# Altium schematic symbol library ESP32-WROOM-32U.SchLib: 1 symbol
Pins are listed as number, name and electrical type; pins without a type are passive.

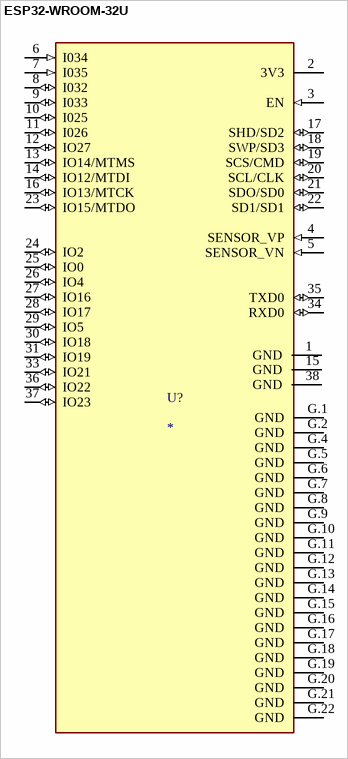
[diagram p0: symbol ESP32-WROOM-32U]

## ESP32-WROOM-32U
designator U?
Bluetooth, WiFi 802.11b/g/n, Bluetooth v4.2 +EDR, Class 1, 2 and 3 Transceiver Module 2.4GHz ~ 2.5GHz Antenna Not Included, U.FL Surface Mount; MF: Espressif Systems; MP: ESP32-WROOM-32U
footprint ESP32-WROOM-32U
pins: 1 GND (power), 2 3V3 (power), 3 EN (in), 4 SENSOR_VP (in), 5 SENSOR_VN (in), 6 I034 (in), 7 I035 (in), 8 I032 (io), 9 I033 (io), 10 I025 (io), 11 I026 (io), 12 IO27 (io), 13 IO14/MTMS (io), 14 IO12/MTDI (io), 15 GND (power), 16 IO13/MTCK (io), 17 SHD/SD2 (io), 18 SWP/SD3 (io), 19 SCS/CMD (io), 20 SCL/CLK (io), 21 SDO/SD0 (io), 22 SD1/SD1 (io), 23 IO15/MTDO (io), 24 IO2 (io), 25 IO0 (io), 26 IO4 (io), 27 IO16 (io), 28 IO17 (io), 29 IO5 (io), 30 IO18 (io), 31 IO19 (io), 33 IO21 (io), 34 RXD0 (io), 35 TXD0 (io), 36 IO22 (io), 37 IO23 (io), 38 GND (power), G.1 GND (power), G.2 GND (power), G.4 GND (power), G.5 GND (power), G.6 GND (power), G.7 GND (power), G.8 GND (power), G.9 GND (power), G.10 GND (power), G.11 GND (power), G.12 GND (power), G.13 GND (power), G.14 GND (power), G.15 GND (power), G.16 GND (power), G.17 GND (power), G.18 GND (power), G.19 GND (power), G.20 GND (power), G.21 GND (power), G.22 GND (power)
